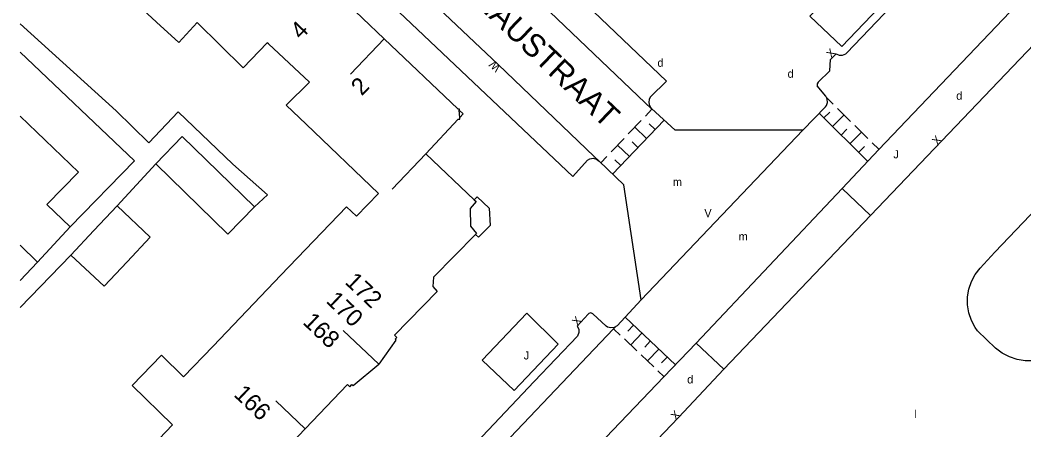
# Model space of a CAD drawing. Extents: x 134999 to 136502, y 457398 to 459002.
# Drawn here: x 135000 to 135061.7, y 457762.7 to 457787.9 of the extents above; entities that cross this region are included whole.
import ezdxf

# ---------------------------------------------------------------- set-up
doc = ezdxf.new("R2010")
doc.units = 0
for name, color, linetype in [('RI_DGTB_15', 7, 'Continuous'), ('RI_DGTB_29', 7, 'Continuous'), ('RI_DGTB_30', 7, 'Continuous'), ('RI_DGTB_31', 7, 'Continuous'), ('RI_DGTB_35', 7, 'Continuous'), ('RI_DGTB_36', 7, 'Continuous'), ('RI_DGTB_37', 7, 'Continuous'), ('RI_DGTB_4', 7, 'Continuous'), ('RI_DGTB_43', 7, 'Continuous'), ('RI_DGTB_5', 7, 'Continuous'), ('RI_DGTB_53', 7, 'Continuous'), ('RI_DGTB_54', 7, 'Continuous'), ('RI_DGTB_6', 7, 'Continuous'), ('RI_DGTB_7', 7, 'Continuous')]:
    doc.layers.add(name, color=color, linetype=linetype)

msp = doc.modelspace()

# ---------------------------------------------------------------- linework, layer by layer
at = {"layer": 'RI_DGTB_15'}
for p, q in [((135022.373, 457786.771), (135020.304, 457784.599)), ((135024.934, 457779.688), (135022.865, 457777.516)), ((135022.027, 457766.767), (135019.856, 457768.838)), ((135017.516, 457762.79), (135015.706, 457764.516))]:
    msp.add_line(p, q, dxfattribs=at)
at = {"layer": 'RI_DGTB_31'}
for p, q in [((135049.548, 457783.138), (135049.951, 457782.743)), ((135038.415, 457782.019), (135038.809, 457782.432)), ((135049.087, 457782.189), (135052.064, 457779.239)), ((135049.377, 457781.901), (135049.734, 457782.253)), ((135050.213, 457782.479), (135051.012, 457781.684)), ((135036.389, 457778.455), (135039.557, 457781.766)), ((135037.361, 457780.918), (135038.151, 457781.744)), ((135039.006, 457781.19), (135038.645, 457781.536)), ((135049.906, 457781.377), (135050.613, 457782.088)), ((135038.479, 457780.64), (135037.757, 457781.331)), ((135050.444, 457780.845), (135050.791, 457781.203)), ((135050.974, 457780.315), (135051.677, 457781.028)), ((135051.281, 457781.427), (135052.077, 457780.632)), ((135036.308, 457779.816), (135037.098, 457780.642)), ((135037.953, 457780.089), (135037.591, 457780.435)), ((135052.343, 457780.372), (135052.743, 457779.975)), ((135037.426, 457779.538), (135036.703, 457780.23)), ((135051.507, 457779.786), (135051.86, 457780.141)), ((135035.67, 457779.149), (135036.045, 457779.541)), ((135036.899, 457778.988), (135036.538, 457779.333)), ((135040.257, 457766.718), (135037.169, 457769.646)), ((135037.683, 457769.165), (135037.337, 457768.802)), ((135036.867, 457768.554), (135036.48, 457768.921)), ((135038.198, 457768.675), (135037.511, 457767.947)), ((135037.894, 457767.577), (135037.123, 457768.314)), ((135038.711, 457768.185), (135038.372, 457767.819)), ((135038.927, 457766.603), (135038.153, 457767.339)), ((135039.231, 457767.693), (135038.54, 457766.966)), ((135039.743, 457767.206), (135039.394, 457766.847)), ((135039.57, 457765.994), (135039.18, 457766.359))]:
    msp.add_line(p, q, dxfattribs=at)
for points in [[(135050.47, 457786.295), (135048.509, 457788.166), (135051.243, 457791.031), (135053.199, 457789.165), (135050.47, 457786.295)], [(135028.386, 457767.006), (135030.345, 457765.148), (135033.062, 457767.993), (135031.129, 457769.898), (135028.386, 457767.006)]]:
    msp.add_lwpolyline(points, dxfattribs=at)
at = {"layer": 'RI_DGTB_4'}
for p, q in [((135018.709, 457790.261), (135022.373, 457786.771)), ((135027.007, 457781.925), (135026.981, 457782.376))]:
    msp.add_line(p, q, dxfattribs=at)
for points in [[(135022.373, 457786.771), (135026.887, 457782.471), (135026.978, 457782.468), (135026.981, 457782.376)], [(135027.007, 457781.925), (135027.22, 457782.154), (135026.981, 457782.376)], [(135024.934, 457779.688), (135026.911, 457781.821), (135027.012, 457781.827), (135027.007, 457781.925)], [(135024.934, 457779.688), (135027.897, 457776.877)], [(135027.897, 457776.877), (135028.013, 457776.767), (135027.647, 457776.344), (135027.667, 457775.259), (135028.042, 457774.807), (135027.978, 457774.741)], [(135027.978, 457774.741), (135025.398, 457772.111), (135025.353, 457771.546), (135025.614, 457771.235), (135022.993, 457768.558), (135023.152, 457768.412), (135023.044, 457768.298), (135023.082, 457768.234), (135022.027, 457766.767)], [(135017.516, 457762.79), (135020.109, 457765.51), (135020.255, 457765.37), (135020.376, 457765.51), (135020.452, 457765.459), (135022.027, 457766.767)], [(135017.516, 457762.79), (135015.022, 457760.174), (135015.504, 457758.79), (135014.577, 457757.831), (135014.386, 457757.901)]]:
    msp.add_lwpolyline(points, dxfattribs=at)
at = {"layer": 'RI_DGTB_5'}
for p, q in [((135017.574, 457781.511), (135022.025, 457777.253)), ((135016.019, 457772.231), (135011.852, 457767.881)), ((135003.078, 457756.418), (135009.358, 457763.04))]:
    msp.add_line(p, q, dxfattribs=at)
for points in [[(135007.272, 457788.809), (135008.379, 457787.796)], [(135008.379, 457787.796), (135009.75, 457786.541)], [(135015.264, 457786.449), (135015.186, 457786.522), (135013.704, 457784.989), (135010.873, 457787.767), (135009.75, 457786.541)], [(135015.264, 457786.449), (135017.771, 457784.111), (135016.351, 457782.681), (135017.574, 457781.511)], [(135000, 457785.945), (135007.021, 457779.269), (135003.081, 457775.211)], [(135000, 457782.015), (135003.584, 457778.565), (135001.649, 457776.577), (135003.081, 457775.211)], [(135016.019, 457772.231), (135020.051, 457776.441), (135020.656, 457775.857), (135022.025, 457777.253)], [(135009.358, 457763.04), (135006.892, 457765.448), (135008.677, 457767.312), (135010.036, 457765.985), (135011.852, 457767.881)]]:
    msp.add_lwpolyline(points, dxfattribs=at)
at = {"layer": 'RI_DGTB_53'}
for p, q in [((135049.746, 457784.79), (135049.033, 457784.104)), ((135038.776, 457782.476), (135038.775, 457782.476)), ((135040.244, 457781.142), (135038.776, 457782.476)), ((135038.142, 457770.723), (135048.082, 457781.153)), ((135048.082, 457781.153), (135040.244, 457781.142)), ((135035.563, 457779.252), (135035.562, 457779.252)), ((135037.083, 457777.785), (135035.563, 457779.252)), ((135038.142, 457770.723), (135037.083, 457777.785)), ((135041.529, 457768.064), (135050.498, 457777.56)), ((135050.498, 457777.56), (135052.236, 457775.906)), ((135052.236, 457775.906), (135043.234, 457766.448)), ((135043.234, 457766.448), (135041.529, 457768.064))]:
    msp.add_line(p, q, dxfattribs=at)
for points in [[(135011.058, 457800), (135033.95, 457778.309), (135034.858, 457779.301), (135035.007, 457779.387), (135035.205, 457779.419), (135035.401, 457779.371), (135035.562, 457779.252)], [(135035.262, 457779.539), (135029.363, 457785.192), (135014.378, 457799.376), (135013.728, 457800)], [(135038.394, 457782.839), (135032.538, 457788.423), (135020.447, 457800)], [(135023.14, 457800), (135039.705, 457784.163), (135038.734, 457783.197), (135038.65, 457783.051), (135038.614, 457782.847), (135038.659, 457782.646), (135038.775, 457782.476)], [(135049.746, 457784.79), (135049.782, 457785.501), (135050.13, 457785.838), (135050.322, 457785.763), (135050.527, 457785.765), (135050.716, 457785.846), (135050.792, 457785.908), (135063.588, 457799.315), (135063.7, 457799.49), (135063.738, 457799.694), (135063.698, 457799.898), (135063.639, 457800)], [(135075.154, 457800), (135070.106, 457794.689), (135069.282, 457793.778), (135052.236, 457775.906)], [(135052.74, 457779.964), (135052.747, 457779.971), (135071.838, 457800)], [(135094.761, 457800), (135064.127, 457767.808), (135063.66, 457767.449), (135063.216, 457767.218), (135062.741, 457767.059), (135062.246, 457766.978), (135061.745, 457766.977), (135061.25, 457767.056), (135060.774, 457767.212), (135060.329, 457767.441), (135059.926, 457767.739), (135058.812, 457768.811), (135058.668, 457769.017), (135058.439, 457769.452), (135058.282, 457769.918), (135058.204, 457770.404), (135058.205, 457770.896), (135058.285, 457771.381), (135058.443, 457771.846), (135058.674, 457772.28), (135058.973, 457772.671), (135059.88, 457773.642), (135084.993, 457800)], [(135049.033, 457784.104), (135048.958, 457783.998), (135048.957, 457783.869)], [(135049.548, 457783.121), (135049.493, 457783.233), (135048.957, 457783.869)], [(135038.775, 457782.476), (135038.394, 457782.839)], [(135048.082, 457781.153), (135049.467, 457782.581), (135049.527, 457782.663), (135049.594, 457782.852), (135049.582, 457783.053), (135049.548, 457783.121)], [(135050.498, 457777.56), (135052.74, 457779.964)], [(135035.562, 457779.252), (135035.262, 457779.539)], [(135038.142, 457770.723), (135036.682, 457769.126), (135036.502, 457769.021), (135036.295, 457768.991), (135036.093, 457769.04), (135035.993, 457769.099), (135035.177, 457769.858), (135035.064, 457769.911), (135034.941, 457769.886), (135034.891, 457769.844), (135034.227, 457769.105), (135034.317, 457768.922), (135034.329, 457768.718), (135034.239, 457768.486), (135031.576, 457765.695)], [(135000, 457730.583), (135036.454, 457768.928)], [(135036.454, 457768.928), (135036.551, 457769.03)], [(135039.552, 457765.995), (135041.529, 457768.064)], [(135000, 457721.089), (135009.332, 457730.836), (135025.199, 457747.511), (135040.447, 457763.479), (135043.234, 457766.448)], [(135000, 457724.463), (135021.703, 457747.315), (135039.552, 457765.995)], [(135018.918, 457752.951), (135019.266, 457753.288), (135019.458, 457753.213), (135019.663, 457753.215), (135019.852, 457753.296), (135019.928, 457753.358), (135031.576, 457765.695)]]:
    msp.add_lwpolyline(points, dxfattribs=at)
at = {"layer": 'RI_DGTB_54'}
for p, q in [((135005.9, 457782.339), (135000, 457787.689)), ((135005.954, 457776.492), (135008.331, 457779.084)), ((135003.081, 457775.211), (135001.078, 457773.04)), ((135000, 457770.247), (135003.114, 457773.472))]:
    msp.add_line(p, q, dxfattribs=at)
msp.add_lwpolyline([(135005.9, 457782.339), (135007.906, 457780.362), (135009.711, 457782.281), (135013.061, 457779.051), (135015.191, 457777.182), (135014.401, 457776.429)], dxfattribs=at)
at = {"layer": 'RI_DGTB_6'}
for points in [[(135014.401, 457776.429), (135009.961, 457780.759), (135008.331, 457779.084)], [(135008.331, 457779.084), (135012.771, 457774.754), (135014.401, 457776.429)], [(135004.533, 457774.98), (135005.954, 457776.492)], [(135005.954, 457776.492), (135007.993, 457774.57), (135006.579, 457773.063)], [(135003.114, 457773.472), (135004.533, 457774.98)], [(135000, 457774.076), (135001.078, 457773.04)], [(135001.078, 457773.04), (135000, 457771.912)], [(135006.579, 457773.063), (135005.163, 457771.553), (135003.114, 457773.472)]]:
    msp.add_lwpolyline(points, dxfattribs=at)
at = {"layer": 'RI_DGTB_7'}
for p, q in [((135027.897, 457776.877), (135028.07, 457777.059)), ((135028.07, 457777.059), (135028.809, 457776.356)), ((135028.809, 457776.356), (135028.868, 457775.298)), ((135028.868, 457775.298), (135028.157, 457774.567))]:
    msp.add_line(p, q, dxfattribs=at)
msp.add_lwpolyline([(135028.157, 457774.567), (135027.978, 457774.741)], dxfattribs=at)

# ---------------------------------------------------------------- texts
at = {"layer": 'RI_DGTB_29'}
for p in [(135039.152, 457785.046), (135047.147, 457784.371), (135057.506, 457783.021), (135040.979, 457765.58)]:
    msp.add_text('d', height=0.5, dxfattribs=at).set_placement(p)
at = {"layer": 'RI_DGTB_30'}
for s, height, rotation, p in [('X', 0.499, 46.46737, (135049.831, 457785.549)), ('W', 0.5, 136.22619, (135029.561, 457785.038)), ('X', 0.5, 47.86969, (135056.34, 457780.2)), ('X', 0.5, 48.69765, (135034.231, 457769.094)), ('X', 0.5, 46.32092, (135040.275, 457763.298))]:
    msp.add_text(s, height=height, rotation=rotation, dxfattribs=at).set_placement(p)
msp.add_text('V', height=0.5, dxfattribs=at).set_placement((135042.033, 457775.8))
at = {"layer": 'RI_DGTB_31'}
for p in [(135053.642, 457779.419), (135030.938, 457767.054)]:
    msp.add_text('J', height=0.5, dxfattribs=at).set_placement(p)
at = {"layer": 'RI_DGTB_35'}
for s, rotation, p in [('2', 46.3912, (135020.988, 457783.215)), ('172', 316.3587, (135019.903, 457771.757))]:
    msp.add_text(s, height=1.054, rotation=rotation, dxfattribs=at).set_placement(p)
at = {"layer": 'RI_DGTB_36'}
for s, rotation, p in [('4', 46.3912, (135017.261, 457786.666)), ('170', 316.367, (135018.741, 457770.596)), ('168', 316.3587, (135017.308, 457769.29)), ('166', 316.3587, (135013.073, 457764.844))]:
    msp.add_text(s, height=1.054, rotation=rotation, dxfattribs=at).set_placement(p)
at = {"layer": 'RI_DGTB_37'}
msp.add_text('KENAUSTRAAT', height=1.4, rotation=316.40159, dxfattribs=at).set_placement((135025.963, 457790.749))
at = {"layer": 'RI_DGTB_43'}
for s, p in [('m', (135040.099, 457777.717)), ('l', (135054.918, 457763.447))]:
    msp.add_text(s, height=0.5, dxfattribs=at).set_placement(p)
msp.add_text('m', height=0.5, rotation=0.16348, dxfattribs=at).set_placement((135044.145, 457774.369))

doc.saveas('drawing.dxf')
